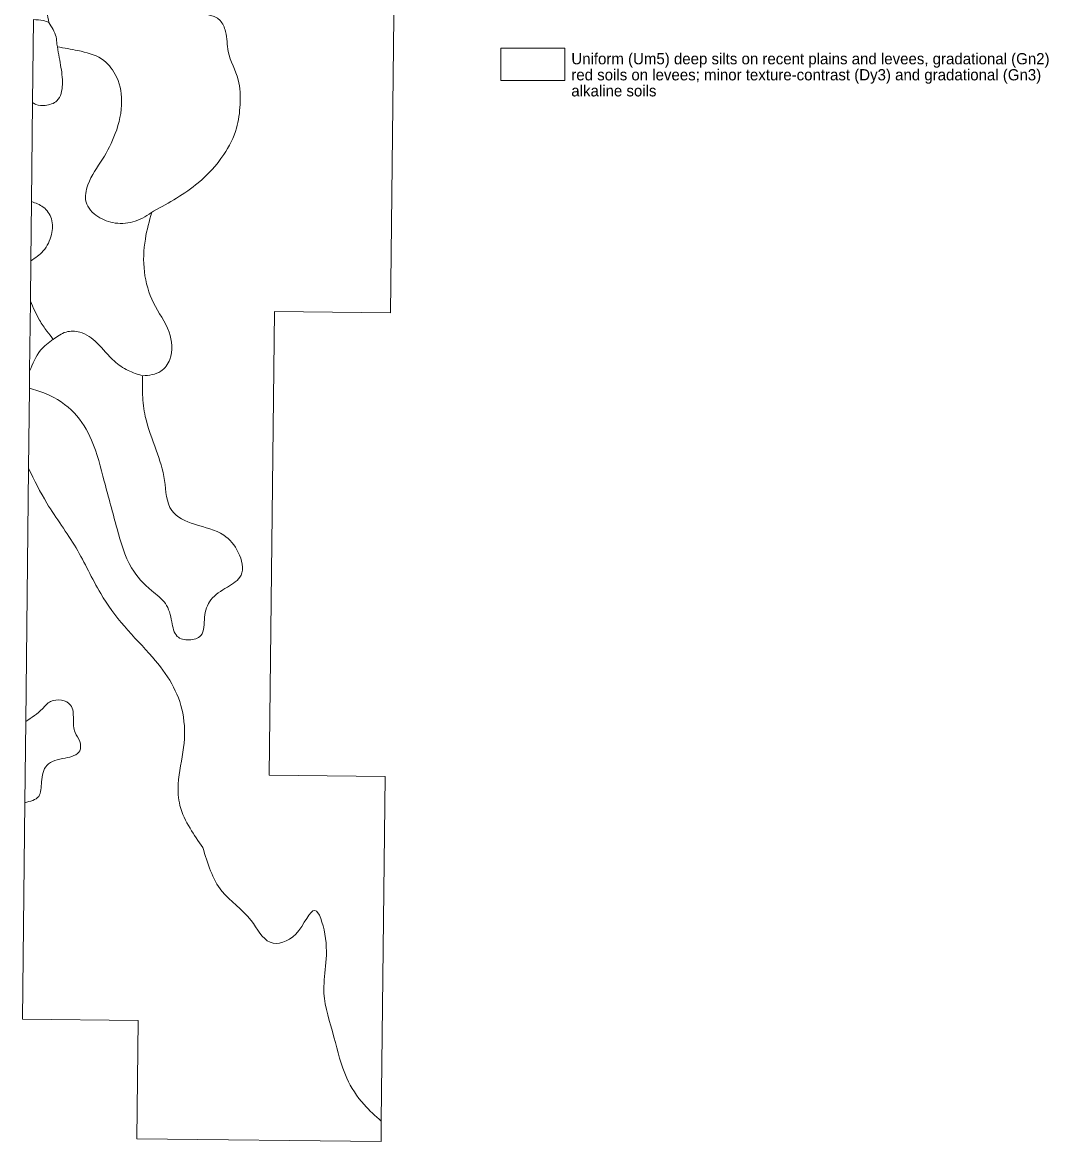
# Model space of a CAD drawing. Extents: x 796677 to 815296, y 8501154 to 8534584.
# Drawn here: x 796677 to 812671, y 8501154 to 8518597 of the extents above; entities that cross this region are included whole.
import ezdxf

# ---------------------------------------------------------------- set-up
doc = ezdxf.new("R2010")
doc.units = 0
doc.header["$LTSCALE"] = 70
for name, color, linetype, lineweight in [('30', 7, 'Continuous', 13), ('31', 7, 'Continuous', 13), ('32', 7, 'Continuous', 13), ('33', 7, 'Continuous', 13)]:
    doc.layers.add(name, color=color, linetype=linetype, lineweight=lineweight)
doc.layers.add('60', color=7, linetype='Continuous')

msp = doc.modelspace()

# ---------------------------------------------------------------- linework, layer by layer
at = {"layer": '30'}
msp.add_line((796786.65, 8512895.02), (796772.74, 8511643.95), dxfattribs=at)
msp.add_lwpolyline([(802270.49, 8501474.58), (802331.51, 8506844.03), (800525.82, 8506864.46), (800607.09, 8514090.19), (802413.3, 8514069.87), (802537.73, 8525140.62), (804070.16, 8525123.41), (805316.55, 8528800.06), (806000.72, 8528792.3), (805979.73, 8526947.23), (811593.82, 8526882.94), (811621.58, 8529294.51)], dxfattribs=at)
for points in [[(798052.52, 8519854.67), (798238.43, 8519549.61), (798494.06, 8519222.71), (798920.11, 8518838.96), (799303.56, 8518739.47), (799758.02, 8518625.77), (799843.23, 8518455.21), (799885.83, 8518142.52), (800042.05, 8517701.92), (800070.46, 8517318.17), (800013.65, 8516948.63), (799814.83, 8516536.45), (799417.18, 8516095.85), (798721.29, 8515655.24)], [(798694.85, 8515640.69), (798593.47, 8515220.49), (798579.27, 8514708.82), (798721.29, 8514225.58), (798962.72, 8513770.76), (798976.92, 8513344.37), (798834.9, 8513159.6), (798550.87, 8513088.54)], [(798550.87, 8513088.54), (798550.83, 8512795.02), (798593.44, 8512453.91), (798763.86, 8511928.02), (798891.67, 8511458.99), (799005.29, 8510989.96), (799360.33, 8510776.77), (799814.79, 8510606.21), (800042.02, 8510336.16), (800084.63, 8509980.84), (799871.6, 8509796.07), (799615.97, 8509597.09), (799516.55, 8509327.04), (799459.75, 8509042.78), (799275.12, 8508971.71), (799090.5, 8509028.57), (799005.29, 8509255.97), (798905.88, 8509540.24), (798692.85, 8509739.22), (798380.41, 8510094.54), (798153.18, 8510705.7), (797954.36, 8511444.78), (797755.53, 8512084.37), (797485.7, 8512510.76), (797045.44, 8512809.23), (796786.65, 8512895.02)], [(796772.74, 8511643.95), (797059.64, 8511103.67), (797514.1, 8510407.23), (797897.55, 8509696.58), (798266.8, 8509184.91), (798707.05, 8508701.67), (799005.29, 8508289.49), (799175.71, 8507834.67), (799189.91, 8507294.58), (799104.7, 8506726.06), (799133.69, 8506392.75), (799289.91, 8506037.42), (799488.73, 8505738.95)], [(799488.73, 8505738.95), (799786.97, 8505056.72), (800241.43, 8504601.91), (800539.66, 8504260.79), (800937.32, 8504388.71), (801235.55, 8504758.25), (801391.77, 8504388.71), (801377.57, 8503464.87), (801533.79, 8502782.64), (801732.62, 8502143.05), (802002.45, 8501730.88), (802270.49, 8501474.58)]]:
    msp.add_spline(points, degree=3, dxfattribs=at)
at = {"layer": '31'}
for p, q in [((797155.28, 8513661.96), (797159.09, 8513657.06)), ((796786.59, 8512889.32), (796789.6, 8513159.92))]:
    msp.add_line(p, q, dxfattribs=at)
msp.add_lwpolyline([(796714.84, 8506435.91), (796728.99, 8507708.56), (796728.9, 8507700.71)], dxfattribs=at)
for points in [[(798052.52, 8519854.67), (797869.18, 8519677.53), (797471.53, 8519521.19), (797144.89, 8519307.99), (797002.87, 8519037.94), (797059.68, 8518753.68), (797088.08, 8518597.34)], [(798721.29, 8515655.24), (799417.18, 8516095.85), (799814.83, 8516536.45), (800013.65, 8516948.63), (800070.46, 8517318.17), (800042.05, 8517701.92), (799885.83, 8518142.52), (799843.23, 8518455.21), (799758.02, 8518625.77), (799303.56, 8518739.47), (798920.11, 8518838.96), (798494.06, 8519222.71), (798238.43, 8519549.61), (798052.52, 8519854.67)], [(797088.08, 8518597.34), (797201.69, 8518369.93), (797215.9, 8518256.23)], [(797222.78, 8518216.66), (797542.54, 8518156.74), (797911.78, 8518028.82), (798124.81, 8517787.2), (798224.22, 8517375.02), (798124.81, 8516863.35), (797925.99, 8516465.39), (797698.76, 8516067.42), (797670.35, 8515797.37), (797854.98, 8515569.97), (798124.81, 8515470.47), (798437.25, 8515498.9), (798721.29, 8515655.24)], [(796789.6, 8513159.92), (796960.26, 8513486.5), (797155.28, 8513661.96)], [(797159.09, 8513657.06), (797357.91, 8513770.76), (797570.94, 8513770.76), (797840.77, 8513600.2), (798110.61, 8513315.94), (798323.64, 8513173.81), (798550.87, 8513088.54)], [(798550.87, 8513088.54), (798550.83, 8512795.02), (798593.44, 8512453.91), (798763.86, 8511928.02), (798891.67, 8511458.99), (799005.29, 8510989.96), (799360.33, 8510776.77), (799814.79, 8510606.21), (800042.02, 8510336.16), (800084.63, 8509980.84), (799871.6, 8509796.07), (799615.97, 8509597.09), (799516.55, 8509327.04), (799459.75, 8509042.78), (799275.12, 8508971.71), (799090.5, 8509028.57), (799005.29, 8509255.97), (798905.88, 8509540.24), (798692.85, 8509739.22), (798380.41, 8510094.54), (798153.18, 8510705.7), (797954.36, 8511444.78), (797755.53, 8512084.37), (797485.7, 8512510.76), (797045.44, 8512809.23), (796786.65, 8512895.02)], [(796728.9, 8507700.71), (796989.21, 8507899.33), (797117.03, 8508013.03), (797429.47, 8507956.18), (797472.07, 8507742.99), (797500.48, 8507529.79), (797571.49, 8507387.66), (797571.49, 8507245.53), (797344.26, 8507131.83), (797060.22, 8507018.12), (796975.01, 8506762.29), (796932.41, 8506534.88), (796714.84, 8506435.91)]]:
    msp.add_spline(points, degree=3, dxfattribs=at)
at = {"layer": '32'}
for p, q in [((797215.9, 8518256.23), (797222.78, 8518216.66)), ((796818.98, 8515803.69), (796836.13, 8517346.55)), ((796801.76, 8514254.19), (796808.71, 8514879.64)), ((796772.74, 8511643.95), (796728.9, 8507700.71))]:
    msp.add_line(p, q, dxfattribs=at)
msp.add_lwpolyline([(796714.93, 8506444.04), (796677.33, 8503062.38), (798482.57, 8503042.05), (798461.72, 8501197.01), (802266.85, 8501153.87), (802270.49, 8501474.58)], dxfattribs=at)
for points in [[(798052.52, 8519854.67), (797869.18, 8519677.53), (797471.53, 8519521.19), (797144.89, 8519307.99), (797002.87, 8519037.94), (797059.68, 8518753.68), (797088.08, 8518597.34)], [(797088.08, 8518597.34), (797002.87, 8518625.77), (796850.53, 8518640.09)], [(796836.15, 8517346.55), (796889.25, 8517318.17), (797031.27, 8517303.95), (797215.9, 8517375.02), (797301.11, 8517630.85), (797272.7, 8517929.33), (797215.9, 8518256.23)], [(797222.78, 8518216.66), (797542.54, 8518156.74), (797911.78, 8518028.82), (798124.81, 8517787.2), (798224.22, 8517375.02), (798124.81, 8516863.35), (797925.99, 8516465.39), (797698.76, 8516067.42), (797670.35, 8515797.37), (797854.98, 8515569.97), (798124.81, 8515470.47), (798437.25, 8515498.9), (798721.29, 8515655.24)], [(796808.72, 8514879.64), (797002.87, 8515035.72), (797130.68, 8515291.55), (797130.68, 8515533.18), (797002.87, 8515717.95), (796818.99, 8515803.69)], [(798694.85, 8515640.69), (798593.47, 8515220.49), (798579.27, 8514708.82), (798721.29, 8514225.58), (798962.72, 8513770.76), (798976.92, 8513344.37), (798834.9, 8513159.6), (798550.87, 8513088.54)], [(797159.09, 8513657.06), (797059.68, 8513784.97), (796946.06, 8513955.53), (796801.76, 8514254.19)], [(798550.87, 8513088.54), (798323.64, 8513173.81), (798110.61, 8513315.94), (797840.77, 8513600.2), (797570.94, 8513770.76), (797357.91, 8513770.76), (797159.09, 8513657.06)], [(799488.73, 8505738.95), (799289.91, 8506037.42), (799133.69, 8506392.75), (799104.7, 8506726.06), (799189.91, 8507294.58), (799175.71, 8507834.67), (799005.29, 8508289.49), (798707.05, 8508701.67), (798266.8, 8509184.91), (797897.55, 8509696.58), (797514.1, 8510407.23), (797059.64, 8511103.67), (796772.74, 8511643.95)], [(796728.9, 8507700.71), (796989.21, 8507899.33), (797117.03, 8508013.03), (797429.47, 8507956.18), (797472.07, 8507742.99), (797500.48, 8507529.79), (797571.49, 8507387.66), (797571.49, 8507245.53), (797344.26, 8507131.83), (797060.22, 8507018.12), (796975.01, 8506762.29), (796932.41, 8506534.88), (796714.84, 8506435.91)], [(802270.49, 8501474.58), (802002.45, 8501730.88), (801732.62, 8502143.05), (801533.79, 8502782.64), (801377.57, 8503464.87), (801391.77, 8504388.71), (801235.55, 8504758.25), (800937.32, 8504388.71), (800539.66, 8504260.79), (800241.43, 8504601.91), (799786.97, 8505056.72), (799488.73, 8505738.95)]]:
    msp.add_spline(points, degree=3, dxfattribs=at)
at = {"layer": '33'}
for p, q in [((796836.14, 8517346.39), (796850.52, 8518640.09)), ((796789.59, 8513159.92), (796801.76, 8514254.19))]:
    msp.add_line(p, q, dxfattribs=at)
msp.add_lwpolyline([(804132.47, 8517693.59), (805132.47, 8517693.59), (805132.47, 8518193.59), (804132.47, 8518193.59)], close=True, dxfattribs=at)
msp.add_lwpolyline([(796818.98, 8515803.69), (796808.75, 8514883.53), (796808.72, 8514879.64)], dxfattribs=at)
for points in [[(796850.53, 8518640.09), (797002.87, 8518625.77), (797088.08, 8518597.34)], [(797088.08, 8518597.34), (797201.69, 8518369.93), (797215.9, 8518256.23)], [(797215.9, 8518256.23), (797272.7, 8517929.33), (797301.11, 8517630.85), (797215.9, 8517375.02), (797031.27, 8517303.95), (796889.25, 8517318.17), (796836.15, 8517346.55)], [(796808.72, 8514879.64), (797002.87, 8515035.72), (797130.68, 8515291.55), (797130.68, 8515533.18), (797002.87, 8515717.95), (796818.99, 8515803.69)], [(796801.76, 8514254.19), (796946.06, 8513955.53), (797059.68, 8513784.97), (797159.09, 8513657.06)], [(797155.28, 8513661.96), (796960.26, 8513486.5), (796789.6, 8513159.92)]]:
    msp.add_spline(points, degree=3, dxfattribs=at)

# ---------------------------------------------------------------- texts
at = {"layer": '60'}
for s, p in [('Uniform (Um5) deep silts on recent plains and levees, gradational (Gn2)', (805232.47, 8517943.59)), ('red soils on levees; minor texture-contrast (Dy3) and gradational (Gn3)', (805232.47, 8517693.59)), ('alkaline soils', (805232.47, 8517443.59))]:
    msp.add_text(s, height=175, dxfattribs=at).set_placement(p)

doc.saveas('drawing.dxf')
